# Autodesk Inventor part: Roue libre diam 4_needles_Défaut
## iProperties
Shininess: 64.0
Length Units: 11269
Angle Units: 11279
Time Units: 11290
Mass Units: 11283
Length Display Precision: 3
Angle Display Precision: 2
Compacted: True
Part Number: Roue libre diam 4_needles_Défaut
Document SubType Name: Modeling
Created: 2006-01
Material: Par défaut
Designer: riri
Density: 0.0
Volumn: 0.0
Area: 0.0
PropertySet Name: Model Information
Control State: 0
Master: False
Checked Out: False
Author: riri
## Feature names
1. Base1
